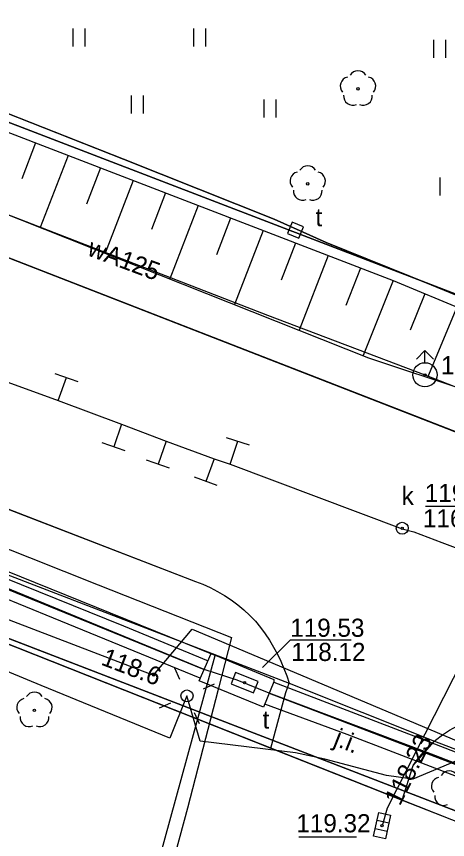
# Model space of a CAD drawing. Extents: x 6432121 to 6432331, y 5662538 to 5662686.
# Drawn here: x 6432225.74 to 6432243.57, y 5662569.04 to 5662603.09 of the extents above; entities that cross this region are included whole.
import ezdxf

# ---------------------------------------------------------------- set-up
doc = ezdxf.new("R2010")
doc.units = 0
for name, color, linetype in [('Warstwa 1', 7, 'Continuous'), ('Warstwa 10', 7, 'Continuous'), ('Warstwa 11', 7, 'Continuous'), ('Warstwa 12', 7, 'Continuous'), ('Warstwa 13', 7, 'Continuous'), ('Warstwa 14', 7, 'Continuous'), ('Warstwa 15', 7, 'Continuous'), ('Warstwa 16', 7, 'Continuous'), ('Warstwa 19', 7, 'Continuous'), ('Warstwa 2', 7, 'Continuous'), ('Warstwa 20', 7, 'Continuous'), ('Warstwa 21', 7, 'Continuous'), ('Warstwa 4', 7, 'Continuous'), ('Warstwa 5', 7, 'Continuous'), ('Warstwa 6', 7, 'Continuous'), ('Warstwa 61', 7, 'Continuous'), ('Warstwa 8', 7, 'Continuous'), ('Warstwa 9', 7, 'Continuous')]:
    doc.layers.add(name, color=color, linetype=linetype)

msp = doc.modelspace()

# ---------------------------------------------------------------- linework, layer by layer
at = {"layer": 'Warstwa 1'}
for p, q in [((6432180.9, 5662615.82), (6432259.074, 5662585.787)), ((6432180.9, 5662615.82), (6432259.074, 5662585.787)), ((6432155.186, 5662604.45), (6432246.621, 5662569.177)), ((6432155.186, 5662604.45), (6432246.621, 5662569.177))]:
    msp.add_line(p, q, dxfattribs=at)
at = {"layer": 'Warstwa 10'}
for p, q in [((6432211.732, 5662603.561), (6432241.32, 5662592.163)), ((6432210.732, 5662600.706), (6432240.306, 5662588.971)), ((6432226.526, 5662597.862), (6432225.954, 5662596.378)), ((6432227.871, 5662597.343), (6432226.721, 5662594.361)), ((6432229.216, 5662596.826), (6432228.638, 5662595.328)), ((6432230.561, 5662596.308), (6432229.402, 5662593.298)), ((6432231.906, 5662595.789), (6432231.324, 5662594.278)), ((6432233.251, 5662595.271), (6432232.081, 5662592.235)), ((6432234.596, 5662594.753), (6432234.008, 5662593.228)), ((6432235.94, 5662594.235), (6432234.76, 5662591.171)), ((6432237.285, 5662593.717), (6432236.692, 5662592.178)), ((6432238.631, 5662593.198), (6432237.44, 5662590.108)), ((6432239.976, 5662592.681), (6432239.368, 5662591.132)), ((6432241.32, 5662592.163), (6432240.08, 5662589.061)), ((6432241.32, 5662592.163), (6432257.132, 5662585.592)), ((6432242.638, 5662591.615), (6432242.025, 5662590.112)), ((6432243.955, 5662591.068), (6432242.745, 5662588.156)), ((6432240.306, 5662588.971), (6432255.183, 5662584.005))]:
    msp.add_line(p, q, dxfattribs=at)
at = {"layer": 'Warstwa 11'}
for centre in [(6432239.868, 5662600.097), (6432237.788, 5662596.167), (6432226.48, 5662574.39)]:
    msp.add_circle(centre, 0.05, dxfattribs=at)
for centre, start, end in [((6432239.868, 5662600.472), 30.1471, 149.8529), ((6432239.511, 5662600.213), 102.1471, 221.8529), ((6432240.225, 5662600.213), 318.1471, 77.8529), ((6432239.648, 5662599.794), 174.1471, 293.8529), ((6432240.088, 5662599.794), 246.1471, 5.8529), ((6432237.431, 5662596.283), 102.1471, 221.8529), ((6432237.788, 5662596.542), 30.1471, 149.8529), ((6432238.145, 5662596.283), 318.1471, 77.8529), ((6432237.568, 5662595.864), 174.1471, 293.8529), ((6432238.008, 5662595.864), 246.1471, 5.8529), ((6432226.123, 5662574.506), 102.1471, 221.8529), ((6432226.48, 5662574.765), 30.1471, 149.8529), ((6432226.837, 5662574.506), 318.1471, 77.8529), ((6432226.26, 5662574.087), 174.1471, 293.8529), ((6432226.7, 5662574.087), 246.1471, 5.8529), ((6432243.64, 5662571.505), 30.1471, 149.8529), ((6432243.283, 5662571.246), 102.1471, 221.8529), ((6432243.42, 5662570.827), 174.1471, 293.8529)]:
    msp.add_arc(centre, 0.375, start, end, dxfattribs=at)
at = {"layer": 'Warstwa 12'}
for points in [[(6432151.934, 5662659.962), (6432163.647, 5662662.364), (6432165.031, 5662661.271), (6432166.026, 5662656.887), (6432167.998, 5662648.227), (6432170.198, 5662638.637), (6432172.215, 5662629.789), (6432174.2, 5662621.336), (6432174.764, 5662618.709), (6432176.004, 5662617.499), (6432181.388, 5662615.664), (6432187.493, 5662613.63), (6432194.563, 5662611.29), (6432209.024, 5662605.561), (6432218.668, 5662601.72), (6432230.17, 5662597.186), (6432236.4, 5662594.702), (6432238.551, 5662593.742), (6432242.89, 5662591.993), (6432244.915, 5662591.158), (6432249.823, 5662589.199), (6432255.518, 5662586.99), (6432264.175, 5662583.483)], [(6432156.818, 5662630.202), (6432158.039, 5662625.384), (6432159.105, 5662620.911), (6432168.554, 5662616.714), (6432182.01, 5662611.519), (6432201.034, 5662604.23), (6432217.284, 5662598.028), (6432236.124, 5662590.737), (6432242.639, 5662588.267), (6432252.12, 5662584.559), (6432258.988, 5662581.806), (6432263.17, 5662580.184), (6432269.496, 5662577.686)], [(6432244.915, 5662591.158), (6432242.89, 5662591.993), (6432238.551, 5662593.742), (6432237.475, 5662594.222), (6432236.4, 5662594.702), (6432230.17, 5662597.186), (6432224.419, 5662599.453), (6432218.668, 5662601.72), (6432209.024, 5662605.561), (6432194.563, 5662611.29), (6432187.493, 5662613.63), (6432176.004, 5662617.499), (6432174.764, 5662618.709), (6432174.2, 5662621.336), (6432172.215, 5662629.789)], [(6432127.185, 5662618.897), (6432135.629, 5662615.848), (6432142.79, 5662613.281), (6432154.997, 5662608.849), (6432160.46, 5662606.879), (6432165.736, 5662604.745), (6432167.852, 5662603.89), (6432175.869, 5662600.716), (6432188.607, 5662595.673), (6432197.141, 5662592.258), (6432208.285, 5662587.853), (6432217.328, 5662584.25), (6432226.269, 5662580.703), (6432229.116, 5662579.575), (6432234.631, 5662577.404), (6432234.076, 5662575.247), (6432232.817, 5662570.334), (6432230.472, 5662561.671), (6432228.926, 5662556.053)], [(6432228.367, 5662556.053), (6432231.658, 5662568.249), (6432233.96, 5662576.659), (6432221.597, 5662581.652), (6432210.31, 5662586.256), (6432196.752, 5662591.605), (6432184.96, 5662596.314), (6432169.081, 5662602.651), (6432160.264, 5662606.196), (6432148.936, 5662610.33), (6432147.827, 5662610.792), (6432135.842, 5662615.166), (6432127.959, 5662618.065)], [(6432220.899, 5662589.591), (6432222.533, 5662588.996), (6432223.084, 5662588.795), (6432227.467, 5662587.21), (6432230.087, 5662586.231), (6432231.926, 5662585.518), (6432233.915, 5662584.796), (6432234.582, 5662584.574), (6432241.702, 5662581.891), (6432242.178, 5662581.775), (6432243.336, 5662581.331), (6432246.139, 5662580.279)], [(6432243.948, 5662572.298), (6432242.135, 5662571.543), (6432241.053, 5662571.693), (6432238.493, 5662572.364), (6432237.277, 5662572.628), (6432233.344, 5662573.109), (6432232.791, 5662574.98), (6432232.085, 5662573.229), (6432226.752, 5662575.417), (6432219.763, 5662578.309), (6432210.104, 5662582.327), (6432202.024, 5662585.528)], [(6432211.625, 5662582.375), (6432212.075, 5662582.545), (6432212.54, 5662583.06), (6432231.41, 5662575.84), (6432233.01, 5662577.75), (6432233.44, 5662577.57), (6432244.03, 5662573.09), (6432248.15, 5662571.43), (6432248.19, 5662569.03), (6432263.02, 5662563.06), (6432265.27, 5662565.67), (6432270.61, 5662563.24), (6432271.806, 5662556.053)], [(6432286.865, 5662556.053), (6432280.878, 5662558.275), (6432269.835, 5662562.391), (6432267.557, 5662563.221), (6432266.199, 5662563.708), (6432264.885, 5662564.131), (6432253.393, 5662568.528), (6432242.726, 5662572.64), (6432236.197, 5662575.094), (6432234.863, 5662575.627), (6432233.503, 5662576.077), (6432221.588, 5662580.986), (6432216.891, 5662582.84), (6432216.154, 5662583.288)], [(6432246.139, 5662580.279), (6432241.073, 5662570.339), (6432240.865, 5662569.613)]]:
    msp.add_lwpolyline(points, dxfattribs=at)
at = {"layer": 'Warstwa 14'}
for p, q in [((6432242.663, 5662582.838), (6432245.023, 5662582.838)), ((6432237.417, 5662569.152), (6432239.809, 5662569.152))]:
    msp.add_line(p, q, dxfattribs=at)
msp.add_lwpolyline([(6432235.911, 5662576.152), (6432237.073, 5662577.302), (6432239.586, 5662577.302)], dxfattribs=at)
for centre in [(6432242.639, 5662588.267), (6432241.699, 5662581.917), (6432241.699, 5662581.917), (6432231.41, 5662575.84), (6432235.175, 5662575.532), (6432235.175, 5662575.532), (6432240.865, 5662569.613), (6432240.865, 5662569.613), (6432240.865, 5662569.613)]:
    msp.add_circle(centre, 0.045, dxfattribs=at)
at = {"layer": 'Warstwa 16'}
msp.add_lwpolyline([(6432233.796, 5662576.738), (6432236.388, 5662575.667), (6432236.386, 5662575.564), (6432235.962, 5662574.517), (6432233.291, 5662575.601)], close=True, dxfattribs=at)
at = {"layer": 'Warstwa 19'}
for p, q in [((6432227.329, 5662588.319), (6432228.272, 5662587.986)), ((6432227.467, 5662587.21), (6432227.8, 5662588.153)), ((6432230.087, 5662586.231), (6432229.76, 5662585.286)), ((6432230.233, 5662585.123), (6432229.288, 5662585.449)), ((6432231.926, 5662585.518), (6432231.595, 5662584.575)), ((6432234.414, 5662585.679), (6432235.366, 5662585.371)), ((6432234.582, 5662584.574), (6432234.89, 5662585.525)), ((6432232.066, 5662584.409), (6432231.123, 5662584.74)), ((6432233.915, 5662584.796), (6432233.574, 5662583.856)), ((6432234.044, 5662583.685), (6432233.104, 5662584.027))]:
    msp.add_line(p, q, dxfattribs=at)
at = {"layer": 'Warstwa 2'}
msp.add_lwpolyline([(6432249.029, 5662556.053), (6432246.97, 5662567.38), (6432245.21, 5662569.28), (6432216.44, 5662580.66), (6432197.427, 5662586.688)], dxfattribs=at)
msp.add_circle((6432232.791, 5662574.98), 0.25, dxfattribs=at)
at = {"layer": 'Warstwa 20'}
for p, q in [((6432211.732, 5662603.561), (6432241.32, 5662592.163)), ((6432241.32, 5662592.163), (6432257.132, 5662585.592))]:
    msp.add_line(p, q, dxfattribs=at)
at = {"layer": 'Warstwa 21'}
for p, q in [((6432210.732, 5662600.706), (6432240.306, 5662588.971)), ((6432240.306, 5662588.971), (6432255.183, 5662584.005))]:
    msp.add_line(p, q, dxfattribs=at)
at = {"layer": 'Warstwa 4'}
for p, q in [((6432240.659, 5662569.838), (6432241.147, 5662569.729)), ((6432240.583, 5662569.497), (6432241.071, 5662569.388))]:
    msp.add_line(p, q, dxfattribs=at)
for points in [[(6432237.146, 5662594.576), (6432236.958, 5662594.112), (6432237.422, 5662593.924), (6432237.61, 5662594.388)], [(6432235.732, 5662575.581), (6432234.801, 5662575.948), (6432234.618, 5662575.483), (6432235.549, 5662575.116)], [(6432240.512, 5662569.18), (6432240.73, 5662570.156), (6432241.218, 5662570.046), (6432241, 5662569.07)]]:
    msp.add_lwpolyline(points, close=True, dxfattribs=at)
for points in [[(6432242.285, 5662588.913), (6432242.639, 5662589.267)], [(6432242.993, 5662588.913), (6432242.639, 5662589.267)], [(6432242.639, 5662588.767), (6432242.639, 5662589.267)], [(6432232.49, 5662575.667), (6432232.29, 5662576.125)], [(6432233.478, 5662575.281), (6432233.936, 5662575.481)], [(6432232.104, 5662574.679), (6432231.646, 5662574.479)], [(6432233.092, 5662574.293), (6432233.292, 5662573.835)]]:
    msp.add_lwpolyline(points, dxfattribs=at)
for centre, radius in [((6432242.639, 5662588.267), 0.5), ((6432241.699, 5662581.917), 0.25)]:
    msp.add_circle(centre, radius, dxfattribs=at)
at = {"layer": 'Warstwa 5'}
for p, q in [((6432211.732, 5662603.561), (6432241.32, 5662592.163)), ((6432228.083, 5662601.849), (6432228.083, 5662602.599)), ((6432228.583, 5662601.849), (6432228.583, 5662602.599)), ((6432233.075, 5662601.85), (6432233.075, 5662602.6)), ((6432233.575, 5662601.85), (6432233.575, 5662602.6)), ((6432243.008, 5662601.38), (6432243.008, 5662602.13)), ((6432243.508, 5662601.38), (6432243.508, 5662602.13)), ((6432230.49, 5662599.078), (6432230.49, 5662599.828)), ((6432230.99, 5662599.078), (6432230.99, 5662599.828)), ((6432235.986, 5662598.908), (6432235.986, 5662599.658)), ((6432236.486, 5662598.908), (6432236.486, 5662599.658)), ((6432243.269, 5662595.684), (6432243.269, 5662596.434)), ((6432241.32, 5662592.163), (6432257.132, 5662585.592)), ((6432210.053, 5662585.902), (6432237.018, 5662575.504)), ((6432216.44, 5662580.66), (6432236.266, 5662572.818)), ((6432216.44, 5662580.66), (6432236.266, 5662572.818)), ((6432236.885, 5662575.124), (6432237.018, 5662575.504)), ((6432236.266, 5662572.818), (6432236.885, 5662575.124)), ((6432236.266, 5662572.818), (6432241.694, 5662570.671)), ((6432242.154, 5662572.1), (6432243.022, 5662573.097)), ((6432243.022, 5662573.097), (6432243.036, 5662573.11)), ((6432243.036, 5662573.11), (6432265.71, 5662564.35)), ((6432241.694, 5662570.671), (6432242.154, 5662572.1)), ((6432241.694, 5662570.671), (6432245.21, 5662569.28)), ((6432241.694, 5662570.671), (6432245.21, 5662569.28))]:
    msp.add_line(p, q, dxfattribs=at)
at = {"layer": 'Warstwa 6'}
for points in [[(6432259.074, 5662585.787), (6432263.163, 5662588.197), (6432246.69, 5662636.13), (6432228.29, 5662630.34), (6432193.86, 5662619.79), (6432180.9, 5662615.82)], [(6432180.9, 5662615.82), (6432147.05, 5662605.45), (6432141.907, 5662600.47), (6432155.186, 5662604.45), (6432246.621, 5662569.177), (6432269.007, 5662560.534), (6432263.163, 5662588.197), (6432259.074, 5662585.787)]]:
    msp.add_lwpolyline(points, close=True, dxfattribs=at)
for points in [[(6432261.892, 5662579.254), (6432260.419, 5662579.482), (6432250.699, 5662583.246), (6432245.014, 5662585.481), (6432215.968, 5662596.774), (6432192.716, 5662605.904), (6432163.326, 5662617.343), (6432161.597, 5662617.988)], [(6432159.72, 5662608.085), (6432174.611, 5662602.284), (6432189.213, 5662596.666), (6432233.139, 5662579.721)], [(6432249.006, 5662556.053), (6432246.621, 5662569.177), (6432155.186, 5662604.45), (6432141.907, 5662600.47), (6432128.788, 5662558.646), (6432132.46, 5662567.032), (6432163.983, 5662578.631), (6432172.647, 5662574.865), (6432180.454, 5662556.053)], [(6432233.139, 5662579.721), (6432233.451, 5662579.599), (6432233.757, 5662579.461), (6432234.054, 5662579.307), (6432234.343, 5662579.137), (6432234.622, 5662578.952), (6432234.891, 5662578.752), (6432235.149, 5662578.538), (6432235.395, 5662578.311), (6432235.629, 5662578.071)], [(6432235.629, 5662578.071), (6432235.834, 5662577.817), (6432236.028, 5662577.554), (6432236.209, 5662577.282), (6432236.377, 5662577.003), (6432236.533, 5662576.715), (6432236.675, 5662576.421), (6432236.803, 5662576.121), (6432236.917, 5662575.815), (6432237.018, 5662575.504)], [(6432242.154, 5662572.1), (6432242.355, 5662572.388), (6432242.578, 5662572.661), (6432242.821, 5662572.915), (6432243.082, 5662573.151), (6432243.36, 5662573.366), (6432243.654, 5662573.56), (6432243.961, 5662573.731), (6432244.281, 5662573.878), (6432244.61, 5662574), (6432244.948, 5662574.098), (6432245.293, 5662574.169), (6432245.642, 5662574.214), (6432245.993, 5662574.233), (6432246.345, 5662574.225), (6432246.695, 5662574.19), (6432247.041, 5662574.129), (6432247.382, 5662574.042), (6432247.715, 5662573.93)]]:
    msp.add_lwpolyline(points, dxfattribs=at)
at = {"layer": 'Warstwa 61'}
for points in [[(6432216.891, 5662582.84), (6432233.502, 5662576.077)], [(6432236.196, 5662575.095), (6432264.885, 5662564.131)]]:
    msp.add_lwpolyline(points, dxfattribs=at)
at = {"layer": 'Warstwa 8'}
for p, q in [((6432215.968, 5662596.774), (6432245.014, 5662585.481)), ((6432192.281, 5662595.483), (6432233.139, 5662579.721)), ((6432233.139, 5662579.721), (6432233.451, 5662579.599)), ((6432233.451, 5662579.599), (6432233.757, 5662579.461)), ((6432233.757, 5662579.461), (6432234.054, 5662579.307)), ((6432234.054, 5662579.307), (6432234.343, 5662579.137)), ((6432234.343, 5662579.137), (6432234.622, 5662578.952)), ((6432234.622, 5662578.952), (6432234.891, 5662578.752)), ((6432234.891, 5662578.752), (6432235.149, 5662578.538)), ((6432235.149, 5662578.538), (6432235.395, 5662578.311)), ((6432235.395, 5662578.311), (6432235.629, 5662578.071)), ((6432235.629, 5662578.071), (6432235.834, 5662577.817)), ((6432235.834, 5662577.817), (6432236.028, 5662577.554)), ((6432233.44, 5662577.57), (6432244.03, 5662573.09)), ((6432236.028, 5662577.554), (6432236.209, 5662577.282)), ((6432236.209, 5662577.282), (6432236.377, 5662577.003)), ((6432236.377, 5662577.003), (6432236.533, 5662576.715)), ((6432236.533, 5662576.715), (6432236.675, 5662576.421)), ((6432236.675, 5662576.421), (6432236.803, 5662576.121)), ((6432236.803, 5662576.121), (6432236.917, 5662575.815)), ((6432236.917, 5662575.815), (6432237.018, 5662575.504)), ((6432236.885, 5662575.124), (6432237.018, 5662575.504)), ((6432237.018, 5662575.504), (6432243.034, 5662573.111)), ((6432237.018, 5662575.504), (6432243.034, 5662573.111)), ((6432236.266, 5662572.818), (6432236.885, 5662575.124)), ((6432243.36, 5662573.366), (6432243.654, 5662573.56)), ((6432243.034, 5662573.111), (6432243.082, 5662573.151)), ((6432243.082, 5662573.151), (6432243.36, 5662573.366)), ((6432236.266, 5662572.818), (6432241.694, 5662570.671)), ((6432242.154, 5662572.1), (6432243.022, 5662573.097)), ((6432243.022, 5662573.097), (6432243.034, 5662573.111)), ((6432241.694, 5662570.671), (6432242.154, 5662572.1))]:
    msp.add_line(p, q, dxfattribs=at)
for points in [[(6432217.063, 5662583.204), (6432223.118, 5662580.727), (6432230.163, 5662577.884), (6432233.662, 5662576.437)], [(6432233.342, 5662575.717), (6432227.275, 5662578.197), (6432219.242, 5662581.477), (6432216.719, 5662582.476)], [(6432236.381, 5662575.551), (6432242.601, 5662573.166), (6432251.115, 5662569.869), (6432254.435, 5662568.551), (6432258.867, 5662566.87), (6432265.02, 5662564.529)], [(6432264.749, 5662563.733), (6432257.833, 5662566.304), (6432248.226, 5662570.002), (6432239.427, 5662573.383), (6432236.011, 5662574.638)]]:
    msp.add_lwpolyline(points, dxfattribs=at)
at = {"layer": 'Warstwa 9'}
for p, q in [((6432210.732, 5662600.706), (6432240.306, 5662588.971)), ((6432215.968, 5662596.774), (6432245.014, 5662585.481)), ((6432192.281, 5662595.483), (6432233.139, 5662579.721)), ((6432240.306, 5662588.971), (6432255.183, 5662584.005)), ((6432210.053, 5662585.902), (6432237.018, 5662575.504)), ((6432233.139, 5662579.721), (6432233.451, 5662579.599)), ((6432233.451, 5662579.599), (6432233.757, 5662579.461)), ((6432233.757, 5662579.461), (6432234.054, 5662579.307)), ((6432234.054, 5662579.307), (6432234.343, 5662579.137)), ((6432234.343, 5662579.137), (6432234.622, 5662578.952)), ((6432234.622, 5662578.952), (6432234.891, 5662578.752)), ((6432234.891, 5662578.752), (6432235.149, 5662578.538)), ((6432235.149, 5662578.538), (6432235.395, 5662578.311)), ((6432235.395, 5662578.311), (6432235.629, 5662578.071)), ((6432235.629, 5662578.071), (6432235.834, 5662577.817)), ((6432235.834, 5662577.817), (6432236.028, 5662577.554)), ((6432236.028, 5662577.554), (6432236.209, 5662577.282)), ((6432236.209, 5662577.282), (6432236.377, 5662577.003)), ((6432236.377, 5662577.003), (6432236.533, 5662576.715)), ((6432236.533, 5662576.715), (6432236.675, 5662576.421)), ((6432236.675, 5662576.421), (6432236.803, 5662576.121)), ((6432236.803, 5662576.121), (6432236.917, 5662575.815)), ((6432236.917, 5662575.815), (6432237.018, 5662575.504)), ((6432243.36, 5662573.366), (6432243.654, 5662573.56)), ((6432243.034, 5662573.111), (6432243.082, 5662573.151)), ((6432243.082, 5662573.151), (6432243.36, 5662573.366)), ((6432243.034, 5662573.111), (6432265.71, 5662564.35))]:
    msp.add_line(p, q, dxfattribs=at)

# ---------------------------------------------------------------- texts
at = {"layer": 'Warstwa 13'}
msp.add_text('wA125', height=0.75, rotation=339.5405, dxfattribs=at).set_placement((6432228.625, 5662593.222))
at = {"layer": 'Warstwa 14'}
for s, p in [('116.88', (6432242.557, 5662581.953)), ('118.12', (6432237.109, 5662576.427))]:
    msp.add_text(s, height=0.75, dxfattribs=at).set_placement(p)
for s, rotation, p in [('118.6', 339.065, (6432229.196, 5662576.286)), ('118.23', 63.69, (6432241.603, 5662570.4))]:
    msp.add_text(s, height=0.75, rotation=rotation, dxfattribs=at).set_placement(p)
at = {"layer": 'Warstwa 15'}
for s, p in [('119.56', (6432243.302, 5662588.288)), ('119.56', (6432242.634, 5662583.003)), ('119.53', (6432237.066, 5662577.427)), ('119.32', (6432237.319, 5662569.339))]:
    msp.add_text(s, height=0.75, dxfattribs=at).set_placement(p)
at = {"layer": 'Warstwa 5'}
for s, p in [('t', (6432238.11, 5662594.413)), ('k', (6432241.675, 5662582.886)), ('t', (6432235.919, 5662573.63))]:
    msp.add_text(s, height=0.75, dxfattribs=at).set_placement(p)
at = {"layer": 'Warstwa 8'}
msp.add_text('j.i.', height=0.75, rotation=338.3087, dxfattribs=at).set_placement((6432238.812, 5662572.955))

doc.saveas('drawing.dxf')
